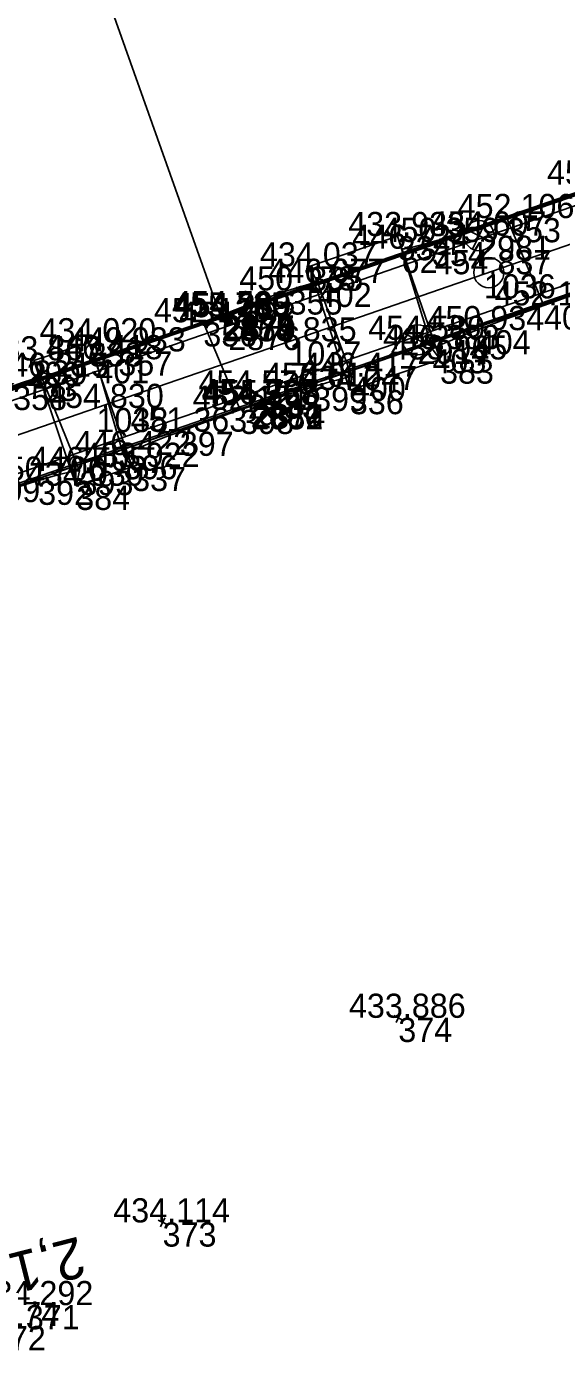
# Model space of a CAD drawing. Extents: x -751615 to -750797, y -1114905 to -1114561.
# Drawn here: x -751130.6 to -751104, y -1114729 to -1114663.2 of the extents above; entities that cross this region are included whole.
import ezdxf

# ---------------------------------------------------------------- set-up
doc = ezdxf.new("R2010")
doc.units = 0
for name, color, linetype in [('Vrstva 1', 7, 'Continuous'), ('Vrstva 17', 7, 'Continuous'), ('Vrstva 18', 7, 'Continuous'), ('Vrstva 4', 7, 'Continuous'), ('Vrstva 48', 7, 'Continuous'), ('Vrstva 49', 7, 'Continuous'), ('Vrstva 60', 7, 'Continuous'), ('Vrstva 61', 7, 'Continuous'), ('Vrstva 63', 7, 'Continuous'), ('Vrstva 7', 7, 'Continuous')]:
    doc.layers.add(name, color=color, linetype=linetype)

msp = doc.modelspace()

# ---------------------------------------------------------------- linework, layer by layer
at = {"layer": 'Vrstva 1'}
msp.add_lwpolyline([(-751049.798, -1114655.49), (-751059.246, -1114658.755), (-751068.733, -1114662.026), (-751078.259, -1114665.311), (-751087.386, -1114668.46), (-751094.716, -1114670.988), (-751098.18, -1114672.185), (-751107.899, -1114675.542), (-751117.566, -1114678.875), (-751127.151, -1114682.181), (-751136.66, -1114685.456), (-751145.831, -1114688.627), (-751153.169, -1114691.158), (-751162.606, -1114694.412), (-751172.056, -1114697.672), (-751181.572, -1114700.954), (-751190.356, -1114703.987), (-751200.827, -1114707.603), (-751207.289, -1114709.832), (-751216.509, -1114713.014)], dxfattribs=at)
at = {"layer": 'Vrstva 17'}
for points in [[(-751100.192, -1114670.473), (-751120.935, -1114677.646), (-751141.741, -1114684.824)], [(-751098.608, -1114674.826), (-751119.351, -1114681.996), (-751140.279, -1114689.211)]]:
    msp.add_lwpolyline(points, dxfattribs=at)
at = {"layer": 'Vrstva 18'}
for p, q in [((-751120.982, -1114677.614), (-751139.734, -1114624.839)), ((-751106.751, -1114672.753), (-751104.913, -1114677.091)), ((-751112.185, -1114673.647), (-751116.573, -1114675.16)), ((-751111.988, -1114674.275), (-751112.185, -1114673.647)), ((-751110.078, -1114679.774), (-751112.185, -1114673.647)), ((-751111.988, -1114674.275), (-751110.455, -1114679.261)), ((-751116.573, -1114675.16), (-751116.152, -1114675.968)), ((-751114.558, -1114681.291), (-751116.573, -1114675.16)), ((-751116.152, -1114675.968), (-751114.459, -1114680.629)), ((-751121.839, -1114677.927), (-751120.009, -1114682.273)), ((-751125.377, -1114685.104), (-751127.53, -1114678.922)), ((-751128.154, -1114686.044), (-751130.264, -1114679.82)), ((-751127.199, -1114679.761), (-751125.802, -1114684.521)), ((-751129.873, -1114680.633), (-751127.991, -1114685.309))]:
    msp.add_line(p, q, dxfattribs=at)
for points in [[(-751047.485, -1114652.852), (-751074.245, -1114662.097), (-751099.037, -1114670.633), (-751120.593, -1114678.106), (-751141.938, -1114685.464), (-751163.608, -1114692.915), (-751187.181, -1114701.023)], [(-751046.217, -1114656.195), (-751073.081, -1114665.441), (-751097.909, -1114674.024), (-751119.627, -1114681.519), (-751140.891, -1114688.815), (-751162.437, -1114696.278), (-751186.019, -1114704.426)], [(-751100.304, -1114670.445), (-751120.868, -1114677.575), (-751141.687, -1114684.707)], [(-751100.314, -1114670.448), (-751120.867, -1114677.58), (-751141.684, -1114684.708)], [(-751100.259, -1114670.569), (-751120.806, -1114677.676), (-751141.644, -1114684.83)], [(-751098.707, -1114674.793), (-751119.481, -1114681.948), (-751140.225, -1114689.091)], [(-751098.67, -1114674.898), (-751119.447, -1114682.04), (-751140.213, -1114689.205)], [(-751098.671, -1114674.893), (-751119.447, -1114682.041), (-751140.176, -1114689.183)], [(-751120.593, -1114678.106), (-751120.868, -1114677.575), (-751120.867, -1114677.58), (-751120.806, -1114677.676)], [(-751127.199, -1114679.761), (-751127.53, -1114678.922), (-751130.264, -1114679.82), (-751129.873, -1114680.633)], [(-751114.459, -1114680.629), (-751114.558, -1114681.291), (-751110.078, -1114679.774), (-751110.455, -1114679.261)], [(-751119.627, -1114681.519), (-751119.447, -1114682.041), (-751119.447, -1114682.04), (-751119.481, -1114681.948)], [(-751127.991, -1114685.309), (-751128.154, -1114686.044), (-751125.377, -1114685.104), (-751125.802, -1114684.521)]]:
    msp.add_lwpolyline(points, dxfattribs=at)
for centre, major_axis, ratio, start_param, end_param in [((-751106.446, -1114672.306), (5.57, 1.95), 0.054548, 4.638587, 6.198968), ((-751106.68, -1114672.46), (-5.315, -1.806), 0.045323, 0.03987, 1.542126), ((-751104.792, -1114677.436), (5.613, 2.021), 0.061329, 0.045958, 1.570185), ((-751121.58, -1114678.169), (5.45, 2.185), 0.054637, 0.070482, 1.596441), ((-751104.796, -1114677.263), (-5.662, -2.008), 0.033513, 4.721234, 6.241131), ((-751121.793, -1114677.908), (-5.406, -1.853), 0.000491, 0.001299, 1.562125), ((-751135.125, -1114682.605), (-5.256, -1.979), 0.01892, 3.094527, 4.748588), ((-751120.106, -1114682.492), (5.654, 1.857), 0.029801, 0.04081, 1.543793), ((-751120.198, -1114682.554), (-5.606, -1.976), 0.034148, 4.666709, 6.243548), ((-751133.613, -1114687.308), (5.631, 1.989), 0.053396, 0.040531, 1.494439)]:
    msp.add_ellipse(centre, major_axis=major_axis, ratio=ratio, start_param=start_param, end_param=end_param, dxfattribs=at)
at = {"layer": 'Vrstva 4'}
for points in [[(-751047.485, -1114652.852), (-751074.245, -1114662.097), (-751099.037, -1114670.633), (-751120.593, -1114678.106), (-751141.938, -1114685.464), (-751163.608, -1114692.915), (-751187.181, -1114701.023)], [(-751046.217, -1114656.195), (-751073.081, -1114665.441), (-751097.909, -1114674.024), (-751119.627, -1114681.519), (-751140.891, -1114688.815), (-751162.437, -1114696.278), (-751186.019, -1114704.426)]]:
    msp.add_lwpolyline(points, dxfattribs=at)
at = {"layer": 'Vrstva 49'}
for p, q in [((-751111.926, -1114712.57), (-751112.376, -1114712.35)), ((-751112.041, -1114712.235), (-751112.261, -1114712.685)), ((-751123.638, -1114722.729), (-751124.088, -1114722.509)), ((-751123.753, -1114722.394), (-751123.973, -1114722.844))]:
    msp.add_line(p, q, dxfattribs=at)
at = {"layer": 'Vrstva 60'}
for p, q in [((-751106.751, -1114672.753), (-751106.751, -1114672.753)), ((-751112.185, -1114673.647), (-751112.185, -1114673.647)), ((-751110.481, -1114673.937), (-751110.481, -1114673.937)), ((-751108.139, -1114673.624), (-751108.139, -1114673.624)), ((-751111.988, -1114674.275), (-751111.988, -1114674.275)), ((-751116.573, -1114675.16), (-751116.573, -1114675.16)), ((-751116.152, -1114675.968), (-751116.152, -1114675.968)), ((-751107.899, -1114675.542), (-751107.899, -1114675.542)), ((-751117.602, -1114676.343), (-751117.602, -1114676.343)), ((-751104.913, -1114677.091), (-751104.913, -1114677.091)), ((-751121.839, -1114677.927), (-751121.839, -1114677.927)), ((-751120.935, -1114677.646), (-751120.935, -1114677.646)), ((-751120.868, -1114677.575), (-751120.868, -1114677.575)), ((-751120.867, -1114677.58), (-751120.867, -1114677.58)), ((-751120.806, -1114677.676), (-751120.806, -1114677.676)), ((-751120.593, -1114678.106), (-751120.593, -1114678.106)), ((-751108.252, -1114678.318), (-751108.252, -1114678.318)), ((-751127.53, -1114678.922), (-751127.53, -1114678.922)), ((-751117.566, -1114678.875), (-751117.566, -1114678.875)), ((-751111.197, -1114678.798), (-751111.197, -1114678.798)), ((-751110.455, -1114679.261), (-751110.455, -1114679.261)), ((-751130.264, -1114679.82), (-751130.264, -1114679.82)), ((-751127.199, -1114679.761), (-751127.199, -1114679.761)), ((-751126.062, -1114679.373), (-751126.062, -1114679.373)), ((-751110.078, -1114679.774), (-751110.078, -1114679.774)), ((-751129.873, -1114680.633), (-751129.873, -1114680.633)), ((-751116.382, -1114681.129), (-751116.382, -1114681.129)), ((-751114.459, -1114680.629), (-751114.459, -1114680.629)), ((-751119.627, -1114681.519), (-751119.627, -1114681.519)), ((-751114.558, -1114681.291), (-751114.558, -1114681.291)), ((-751127.151, -1114682.181), (-751127.151, -1114682.181)), ((-751120.009, -1114682.273), (-751120.009, -1114682.273)), ((-751119.481, -1114681.948), (-751119.481, -1114681.948)), ((-751119.447, -1114682.04), (-751119.447, -1114682.04)), ((-751119.447, -1114682.041), (-751119.447, -1114682.041)), ((-751119.351, -1114681.996), (-751119.351, -1114681.996)), ((-751123.007, -1114683.357), (-751123.007, -1114683.357)), ((-751125.802, -1114684.521), (-751125.802, -1114684.521)), ((-751125.377, -1114685.104), (-751125.377, -1114685.104)), ((-751130.046, -1114685.791), (-751130.046, -1114685.791)), ((-751127.991, -1114685.309), (-751127.991, -1114685.309)), ((-751128.154, -1114686.044), (-751128.154, -1114686.044)), ((-751112.151, -1114712.46), (-751112.151, -1114712.46)), ((-751123.863, -1114722.619), (-751123.863, -1114722.619))]:
    msp.add_line(p, q, dxfattribs=at)
at = {"layer": 'Vrstva 63'}
for p, q in [((-751107.468, -1114673.946), (-751108.807, -1114673.301)), ((-751107.812, -1114672.958), (-751108.464, -1114674.295)), ((-751110.526, -1114679.12), (-751111.865, -1114678.475)), ((-751110.87, -1114678.132), (-751111.522, -1114679.469))]:
    msp.add_line(p, q, dxfattribs=at)
for centre in [(-751108.139, -1114673.624), (-751111.197, -1114678.798)]:
    msp.add_circle(centre, 0.748, dxfattribs=at)
at = {"layer": 'Vrstva 7'}
msp.add_circle((-751107.655, -1114675.461), 0.75, dxfattribs=at)

# ---------------------------------------------------------------- texts
at = {"layer": 'Vrstva 48'}
msp.add_text('2,1', height=2, rotation=194.22348, dxfattribs=at).set_placement((-751128.029, -1114723.307))
at = {"layer": 'Vrstva 60'}
for s, p in [('353', (-751106.751, -1114673.953)), ('334', (-751112.185, -1114674.847)), ('354', (-751110.481, -1114675.137)), ('2981', (-751108.139, -1114674.824)), ('62', (-751111.988, -1114675.475)), ('335', (-751116.573, -1114676.36)), ('402', (-751116.152, -1114677.168)), ('1036', (-751107.899, -1114676.742)), ('355', (-751117.602, -1114677.543)), ('405', (-751104.913, -1114678.291)), ('356', (-751121.839, -1114679.127)), ('2875', (-751120.935, -1114678.846)), ('2877', (-751120.868, -1114678.775)), ('2878', (-751120.867, -1114678.78)), ('2879', (-751120.806, -1114678.876)), ('2876', (-751120.593, -1114679.306)), ('404', (-751108.252, -1114679.518)), ('338', (-751127.53, -1114680.122)), ('1037', (-751117.566, -1114680.075)), ('2914', (-751111.197, -1114679.998)), ('403', (-751110.455, -1114680.461)), ('339', (-751130.264, -1114681.02)), ('401', (-751127.199, -1114680.961)), ('357', (-751126.062, -1114680.573)), ('383', (-751110.078, -1114680.974)), ('63', (-751129.873, -1114681.833)), ('400', (-751114.459, -1114681.829)), ('358', (-751131.29, -1114682.284)), ('399', (-751116.382, -1114682.329)), ('2883', (-751119.627, -1114682.719)), ('2880', (-751119.481, -1114683.148)), ('336', (-751114.558, -1114682.491)), ('1038', (-751127.151, -1114683.381)), ('398', (-751120.009, -1114683.473)), ('2881', (-751119.447, -1114683.24)), ('2882', (-751119.447, -1114683.241)), ('2874', (-751119.351, -1114683.196)), ('397', (-751123.007, -1114684.557)), ('396', (-751125.802, -1114685.721)), ('337', (-751125.377, -1114686.304)), ('392', (-751130.046, -1114686.991)), ('393', (-751127.991, -1114686.509)), ('384', (-751128.154, -1114687.244)), ('374', (-751112.151, -1114713.66)), ('373', (-751123.863, -1114723.819)), ('371', (-751130.657, -1114727.926)), ('372', (-751132.342, -1114728.961))]:
    msp.add_text(s, height=1.2, dxfattribs=at).set_placement(p)
at = {"layer": 'Vrstva 61'}
for s, p in [('450.255', (-751104.762, -1114671.09)), ('452.106', (-751109.203, -1114672.753)), ('433.933', (-751114.637, -1114673.647)), ('450.359', (-751112.935, -1114673.937)), ('454.607', (-751110.591, -1114673.624)), ('446.724', (-751114.439, -1114674.275)), ('434.037', (-751119.025, -1114675.16)), ('454.837', (-751110.351, -1114675.542)), ('450.178', (-751120.056, -1114676.343)), ('446.677', (-751118.604, -1114675.968)), ('452.139', (-751107.367, -1114677.091)), ('455.735', (-751123.391, -1114677.646)), ('454.589', (-751123.322, -1114677.575)), ('454.290', (-751123.318, -1114677.58)), ('454.289', (-751123.26, -1114677.676)), ('452.125', (-751124.295, -1114677.927)), ('454.592', (-751123.041, -1114678.106)), ('450.934', (-751110.703, -1114678.318)), ('434.020', (-751129.981, -1114678.922)), ('454.835', (-751120.022, -1114678.875)), ('454.580', (-751113.648, -1114678.798)), ('433.867', (-751132.716, -1114679.82)), ('446.418', (-751129.653, -1114679.761)), ('449.933', (-751128.514, -1114679.373)), ('446.388', (-751112.909, -1114679.261)), ('433.965', (-751112.534, -1114679.774)), ('450.290', (-751133.741, -1114681.084)), ('446.215', (-751132.329, -1114680.633)), ('450.612', (-751118.83, -1114681.129)), ('446.417', (-751116.911, -1114680.629)), ('454.576', (-751122.079, -1114681.519)), ('434.047', (-751117.01, -1114681.291)), ('454.830', (-751129.602, -1114682.181)), ('452.121', (-751122.366, -1114682.273)), ('454.267', (-751121.933, -1114681.948)), ('454.268', (-751121.901, -1114682.04)), ('454.568', (-751121.901, -1114682.041)), ('455.725', (-751121.807, -1114681.996)), ('451.363', (-751125.459, -1114683.357)), ('446.422', (-751128.25, -1114684.521)), ('433.922', (-751127.825, -1114685.104)), ('446.405', (-751130.447, -1114685.309)), ('450.706', (-751132.498, -1114685.791)), ('434.030', (-751130.605, -1114686.044)), ('452.109', (-751135.743, -1114686.857)), ('433.886', (-751114.603, -1114712.46)), ('434.114', (-751126.314, -1114722.619)), ('434.292', (-751133.105, -1114726.726)), ('432.174', (-751134.793, -1114727.761))]:
    msp.add_text(s, height=1.2, dxfattribs=at).set_placement(p)

doc.saveas('drawing.dxf')
